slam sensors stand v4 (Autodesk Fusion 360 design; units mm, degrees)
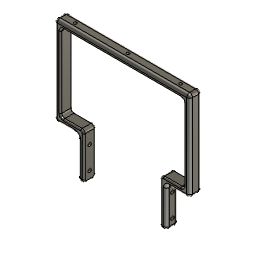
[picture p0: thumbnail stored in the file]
sketch "草图1" plane through (0, 0, 0) normal (1, 0, 0) x axis (0, 1, 0)
  line L1 (-4, -13.25) -> (4, -13.25)
  line L2 (-4, 13.25) -> (-4, -13.25)
  line L3 (4, 13.25) -> (-4, 13.25)
  line L4 (4, -13.25) -> (4, 13.25)
  line L5 (-4, 13.25) -> (4, -13.25)
  line L6 (4, 13.25) -> (-4, -13.25)
  line L7 (4, 0) -> (-4, 0)
  line L8 (0, 0) -> (0, 7.5)
  circle C1 centre (0, 7.5) radius 1.125
  circle C2 centre (0, -7.5) radius 1.125
  point P6 (0, 0)
  point P1 (0, 0)
  point P8 (-4, 0)
  point P9 (4, 0)
  point P7 (0, 7.5)
  point P10 (0, 7.5)
  point P11 (0, 0)
  point P12 (0, -7.5)
  point P2 (4, -13.25)
  point P5 (4, 13.25)
  point P4 (-4, 13.25)
  horizontal L1
  perpendicular L1 L2
  parallel L1 L3
  parallel L2 L4
  coincident L5 P6
  coincident L6 P6
  coincident P1 P6
  midpoint L2 P8
  midpoint L4 P9
  coincident P7 P10
  coincident P6 P11
  perpendicular L7 L8
  symmetric C1 L7 C2
  dimension "d1" diameter C1 = 2.25
  dimension "d2" distance P7 P12 = 15
  dimension "d3" distance P2 P5 = 26.5
  dimension "d4" distance P4 P5 = 8
extrude "拉伸1" new body sketch "草图1" profile of L1 L2 L3 L4 C1 C2 along normal blind 4
sketch "草图2" plane through (0, -4, 0) normal (0, -1, 0) x axis (1, 0, 0)
  line L1 (0, -13.25) -> (0, 13.25)
  line L2 (4, -13.25) -> (0, -13.25)
  line L3 (4, 13.25) -> (4, -13.25)
  line L4 (0, 13.25) -> (4, 13.25)
  line L5 (0, 13.25) -> (4, 13.25)
  line L6 (0, 17.25) -> (0, 13.25)
  line L7 (4, 17.25) -> (0, 17.25)
  line L8 (4, 13.25) -> (4, 17.25)
  line L9 (19.5, 13.25) -> (4, 13.25)
  line L10 (19.5, 20) -> (19.5, 13.25)
  line L11 (19.5, 72.75) -> (19.5, 20)
  line L12 (-25.5, 72.75) -> (19.5, 72.75)
  line L13 (-25.5, 68.75) -> (-25.5, 72.75)
  line L14 (15.5, 68.75) -> (-25.5, 68.75)
  line L15 (15.5, 17.25) -> (15.5, 68.75)
  line L16 (4, 17.25) -> (15.5, 17.25)
  line L17 (0, 13.25) -> (0, -13.25)
  line L18 (4, 13.25) -> (0, 13.25)
  line L19 (4, -13.25) -> (4, 13.25)
  line L20 (0, -13.25) -> (4, -13.25)
  line L21 (0, -13.25) -> (0, 13.25)
  line L22 (4, -13.25) -> (0, -13.25)
  line L23 (4, 13.25) -> (4, -13.25)
  line L24 (0, 13.25) -> (4, 13.25)
  point P5 (4, 13.25)
  point P6 (4, 13.25)
  horizontal L5
  vertical L6
  horizontal L7
  vertical L8
  coincident P5 P6
  collinear L1 L6
  perpendicular L3 L9
  perpendicular L9 L10
  perpendicular L9 L11
  perpendicular L11 L12
  perpendicular L12 L13
  perpendicular L11 L14
  perpendicular L14 L15
  perpendicular L8 L16
  dimension "d7" distance L9 L16 = 4
  dimension "d8" distance L11 L15 = 4
  dimension "d9" distance L12 L14 = 4
  dimension "d10" distance L9 L14 = 55.5
  dimension "d11" distance L1 L13 = 25.5 (= "25.25 mm + 0.25 mm")
  dimension "d16" distance L11 L13 = 45
extrude "拉伸2" add sketch "草图2" profile of L4 L5 L6 L7 L9 L10 L11 L12 L13 L14 L15 L16 L18 L24 to an object
mirror "镜像" mirrorStitchTolerance 0.1
fillet "圆角1" radius 2
fillet "圆角2" radius 2
fillet "圆角3" radius 2
fillet "圆角4" radius 2
sketch "草图3" plane through (0, 0, 72.75) normal (0, 0, 1) x axis (-1, 0, 0)
  line L1 (-17.5, 2) -> (68.5, 2)
  line L2 (-17.5, -2) -> (-17.5, 2)
  line L3 (68.5, -2) -> (-17.5, -2)
  line L4 (68.5, 2) -> (68.5, -2)
  line L5 (25.5, -2) -> (25.5, 2)
  circle C1 centre (25.5, 0) radius 0.975
  circle C2 centre (-9.5, 0) radius 0.975
  circle C3 centre (60.5, 0) radius 0.975
  point P6 (25.5, 2)
  point P7 (25.5, -2)
  point P8 (25.5, 0)
  midpoint L1 P6
  midpoint L3 P7
  midpoint L5 P8
  dimension "d26" diameter C1 = 1.95
  dimension "d29" R-Pattern1-uDistance = 35
  dimension "d30" R-Pattern1-vDistance = 0
extrude "拉伸3" cut sketch "草图3" profile of C1 C2 C3 to an object
fillet "圆角5" radius 1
